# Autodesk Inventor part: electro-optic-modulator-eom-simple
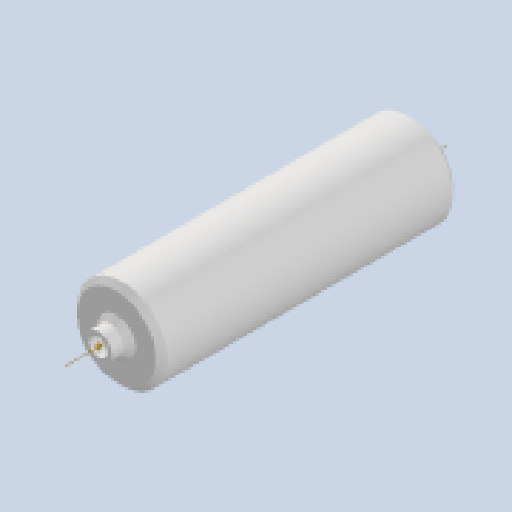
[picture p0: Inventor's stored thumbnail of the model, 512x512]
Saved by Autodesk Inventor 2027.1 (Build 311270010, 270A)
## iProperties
Created: 2026-07
Part Number: electro-optic-modulator-eom-simple
Material: Generic
Document SubType Name: Modeling
Designer: dunge
Density: 1 g/cm^3
Appearance: Default
Author: dunge
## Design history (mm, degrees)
sketch "Sketch1"
  geometry: L1 (12.7, 83.82)-(12.7, 0); L2 (12.7, 0)-(2.54, 0); L3 (2.54, 0)-(2.54, 88.9); L4 (2.54, 88.9)-(3.81, 88.9); L5 (3.81, 88.9)-(3.81, 83.82); L6 (3.81, 83.82)-(12.7, 83.82); L7 (0, 0)-(0, 88.9); 1 further point; 2 other entities
  constraints: 15 end point, 5 perpendicular, 2 coincident, 2 vertical, 1 horizontal, 1 horizontal alignment, 4 other
  dimensions: "d1" = 88.9 distance of L2.end L3.end; "d2" = 5.08 distance of L4.end L5.end; "d4" = 1.27 distance of L3.end L4.end; "d7" = 2.54 distance from line of L7.start L3; "d8" = 12.7 distance from line of L7.start L1
revolve "Revolution1" sketch "Sketch1" stored, may be unused: angle "d6" = 360 deg
workpoint "Work Point1"
  workaxis "Work Axis1"
chamfer "Chamfer1" distance "d9" = 1.5875; stored, may be unused: second distance "d10" = 3.175, angle "d11" = 45 deg
body "Solid1"
